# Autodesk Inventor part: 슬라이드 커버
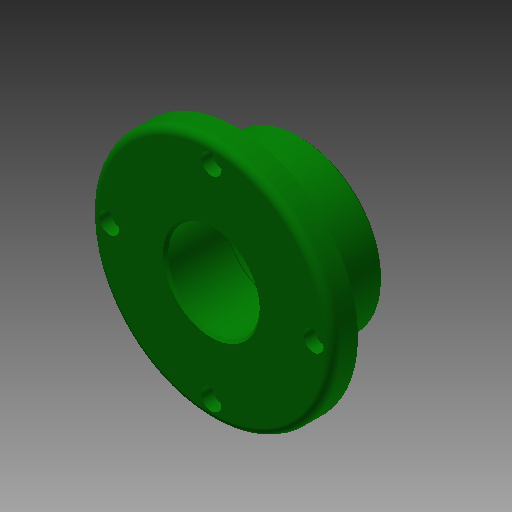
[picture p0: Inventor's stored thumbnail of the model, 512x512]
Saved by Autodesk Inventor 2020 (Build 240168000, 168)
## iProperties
Created: 2015-10
Part Number: 슬라이드 커버
Document SubType Name: Modeling
Designer: mdu
Density: 7.86 g/cm^3
Material: 강철, 연강
Mass: 598.523 g
Surface Area: 229.996 cm^2
Volume: 76.148 cm^3
Appearance: 진녹색
Author: mdu
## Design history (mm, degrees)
sketch "스케치1"
  geometry: C1 r 47.5 at (0, 0); C2 r 32.5 at (0, 0); 1 further point
  constraints: 2 centre point, 2 coincident
  dimensions: "d33" = 95 diameter of C1; "d35" = 65 diameter of C2
extrude "돌출1" new body sketch "스케치1" distance "d0" = 10; taper "d1" = 0 deg
extrude "돌출2" join sketch "스케치1" distance "d2" = 25; taper "d3" = 0 deg
hole "구멍1" diameter "d6" = 36; stored, may be unused: countersink angle "d10" = 90 deg, drill point angle "d12" = 118 deg; dims "d7" = 6, "d8" = 4, "d9" = 2, "d11" = 8, "d41" = 10, "d42" = 10
sketch "스케치2" dims "d36" = 80
  geometry: 4 further points
  constraints: 2 coincident, 2 vertical alignment, 2 other
hole "구멍2" sketch "스케치2" at (0, 40) diameter "d13" = 4.5; stored, may be unused: countersink angle "d17" = 90 deg, drill point angle "d19" = 118 deg; dims "d14" = 6, "d15" = 8, "d16" = 4.4, "d18" = 8
fillet "모깎기1" dims "d23" = 3
chamfer "모따기1" distance "d24" = 1; stored, may be unused: second distance "d25" = 2, angle "d26" = 45 deg
sketch "스케치3"
  geometry: C1 r 26 at (0, 0); C2 r 19 at (0, 0) reference; 1 further point
  constraints: 1 centre point, 1 concentric
  dimensions: "d27" = 52 diameter of C1
extrude "돌출3" cut sketch "스케치3" distance "d28" = 10; taper "d29" = 0 deg
chamfer "모따기2" distance "d30" = 1; stored, may be unused: second distance "d31" = 2, angle "d32" = 45 deg
node "솔리드1"
pattern_circular "원형 패턴1" dims angle "d21" = 360 deg
